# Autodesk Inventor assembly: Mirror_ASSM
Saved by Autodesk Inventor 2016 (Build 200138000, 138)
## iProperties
Created: 2015-11
Part Number: Mirror_ASSM
Document SubType Name: Assembly
Designer: John
Author: John
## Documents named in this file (14)
- D:\3D Printer Designs\John Ledden Designs\DLP Printer\V0-4\Mirror_ASSM.iam
- D:\3D Printer Designs\John Ledden Designs\DLP Printer\V0-4\Mirror_Side.ipt
- D:\3D Printer Designs\John Ledden Designs\DLP Printer\V0-4\Mirror_Back.ipt
- D:\3D Printer Designs\John Ledden Designs\DLP Printer\V0-4\Mirror_Holder.ipt
- D:\3D Printer Designs\John Ledden Designs\DLP Printer\V0-4\Disc_magnet.ipt
- D:\3D Printer Designs\John Ledden Designs\DLP Printer\V0-4\Mirror_4InchSq.ipt
- D:\3D Printer Designs\John Ledden Designs\DLP Printer\V0-4\Clamp.ipt
- D:\3D Printer Designs\John Ledden Designs\DLP Printer\V0-4\M6_Rod.ipt
- D:\3D Printer Designs\John Ledden Designs\DLP Printer\V0-4\M5_30.ipt
- D:\3D Printer Designs\John Ledden Designs\DLP Printer\V0-4\M5_Nut.ipt
- D:\3D Printer Designs\John Ledden Designs\DLP Printer\V0-4\M3_10.ipt
- D:\3D Printer Designs\John Ledden Designs\DLP Printer\V0-4\M3_20.ipt
- D:\3D Printer Designs\John Ledden Designs\DLP Printer\V0-4\M3_Nut.ipt
- D:\3D Printer Designs\John Ledden Designs\DLP Printer\V0-4\M6_Nut.ipt
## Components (44 placed, 44 different names)
1. Mirror_Side_1142
2. Mirror_Side_1143
3. Mirror_Back_1144
4. Mirror_Holder_1145
5. Disc_magnet_1146
6. Disc_magnet_1147
7. Mirror_4InchSq_1148
8. Clamp_1149
9. Clamp_1150
10. Clamp_1151
11. Clamp_1152
12. M6_Rod_1153
13. M5_30_1154
14. M5_Nut_1155
15. M3_10_1156
16. M3_20_1157
17. M3_Nut_1158
18. M5_30_1159
19. M5_30_1160
20. M5_30_1161
21. M5_Nut_1162
22. M5_Nut_1163
23. M5_Nut_1164
24. M5_Nut_1165
25. M5_30_1166
26. M5_30_1167
27. M5_Nut_1168
28. M5_30_1169
29. M5_Nut_1170
30. M5_30_1171
31. M5_Nut_1172
32. M3_Nut_1173
33. M3_Nut_1174
34. M3_Nut_1175
35. M3_10_1176
36. M3_10_1177
37. M3_10_1178
38. M3_20_1179
39. M3_20_1180
40. M3_20_1181
41. M3_Nut_1182
42. M3_Nut_1183
43. M6_Nut_1184
44. M6_Nut_1185
